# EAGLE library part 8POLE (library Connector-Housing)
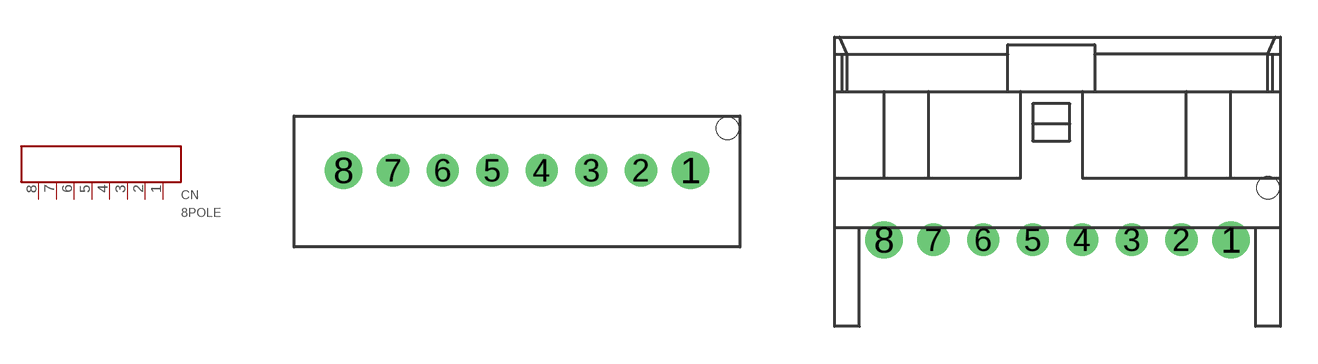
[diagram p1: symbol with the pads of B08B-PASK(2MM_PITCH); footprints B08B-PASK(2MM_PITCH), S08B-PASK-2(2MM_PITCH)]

Designator prefix CN

## 8POLE-PASK  [B08B-PASK(2MM_PITCH)]
1  P$8
2  P$7
3  P$6
4  P$5
5  P$4
6  P$3
7  P$2
8  P$1

## 8POLE-PASK_SIDE  [S08B-PASK-2(2MM_PITCH)]
Pads as for B08B-PASK(2MM_PITCH)

## Footprint B08B-PASK(2MM_PITCH) (pad centres in mm)
B08B-PASK _PA series 2.0mm pitch connector Producted by JST.
drill 1 round: 1 7,0; 8 -7,0
drill 0.8 round: 2 5,0; 3 3,0; 4 1,0; 5 -1,0; 6 -3,0; 7 -5,0
hole 0.9 at 8.5,1.7

## Footprint S08B-PASK-2(2MM_PITCH) (pad centres in mm)
S08B-PASK _PA series 2.0mm pitch connector Producted by JST.
drill 1 round: 1 7,0; 8 -7,0
drill 0.8 round: 2 5,0; 3 3,0; 4 1,0; 5 -1,0; 6 -3,0; 7 -5,0
hole 0.9 at 8.5,2.1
